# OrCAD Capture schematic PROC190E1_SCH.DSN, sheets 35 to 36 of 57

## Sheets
35 36. CPSW3G RGMII_1: size C; title: ETHERNET EXPANSION CONNECTOR CPSW3G RGMII 1
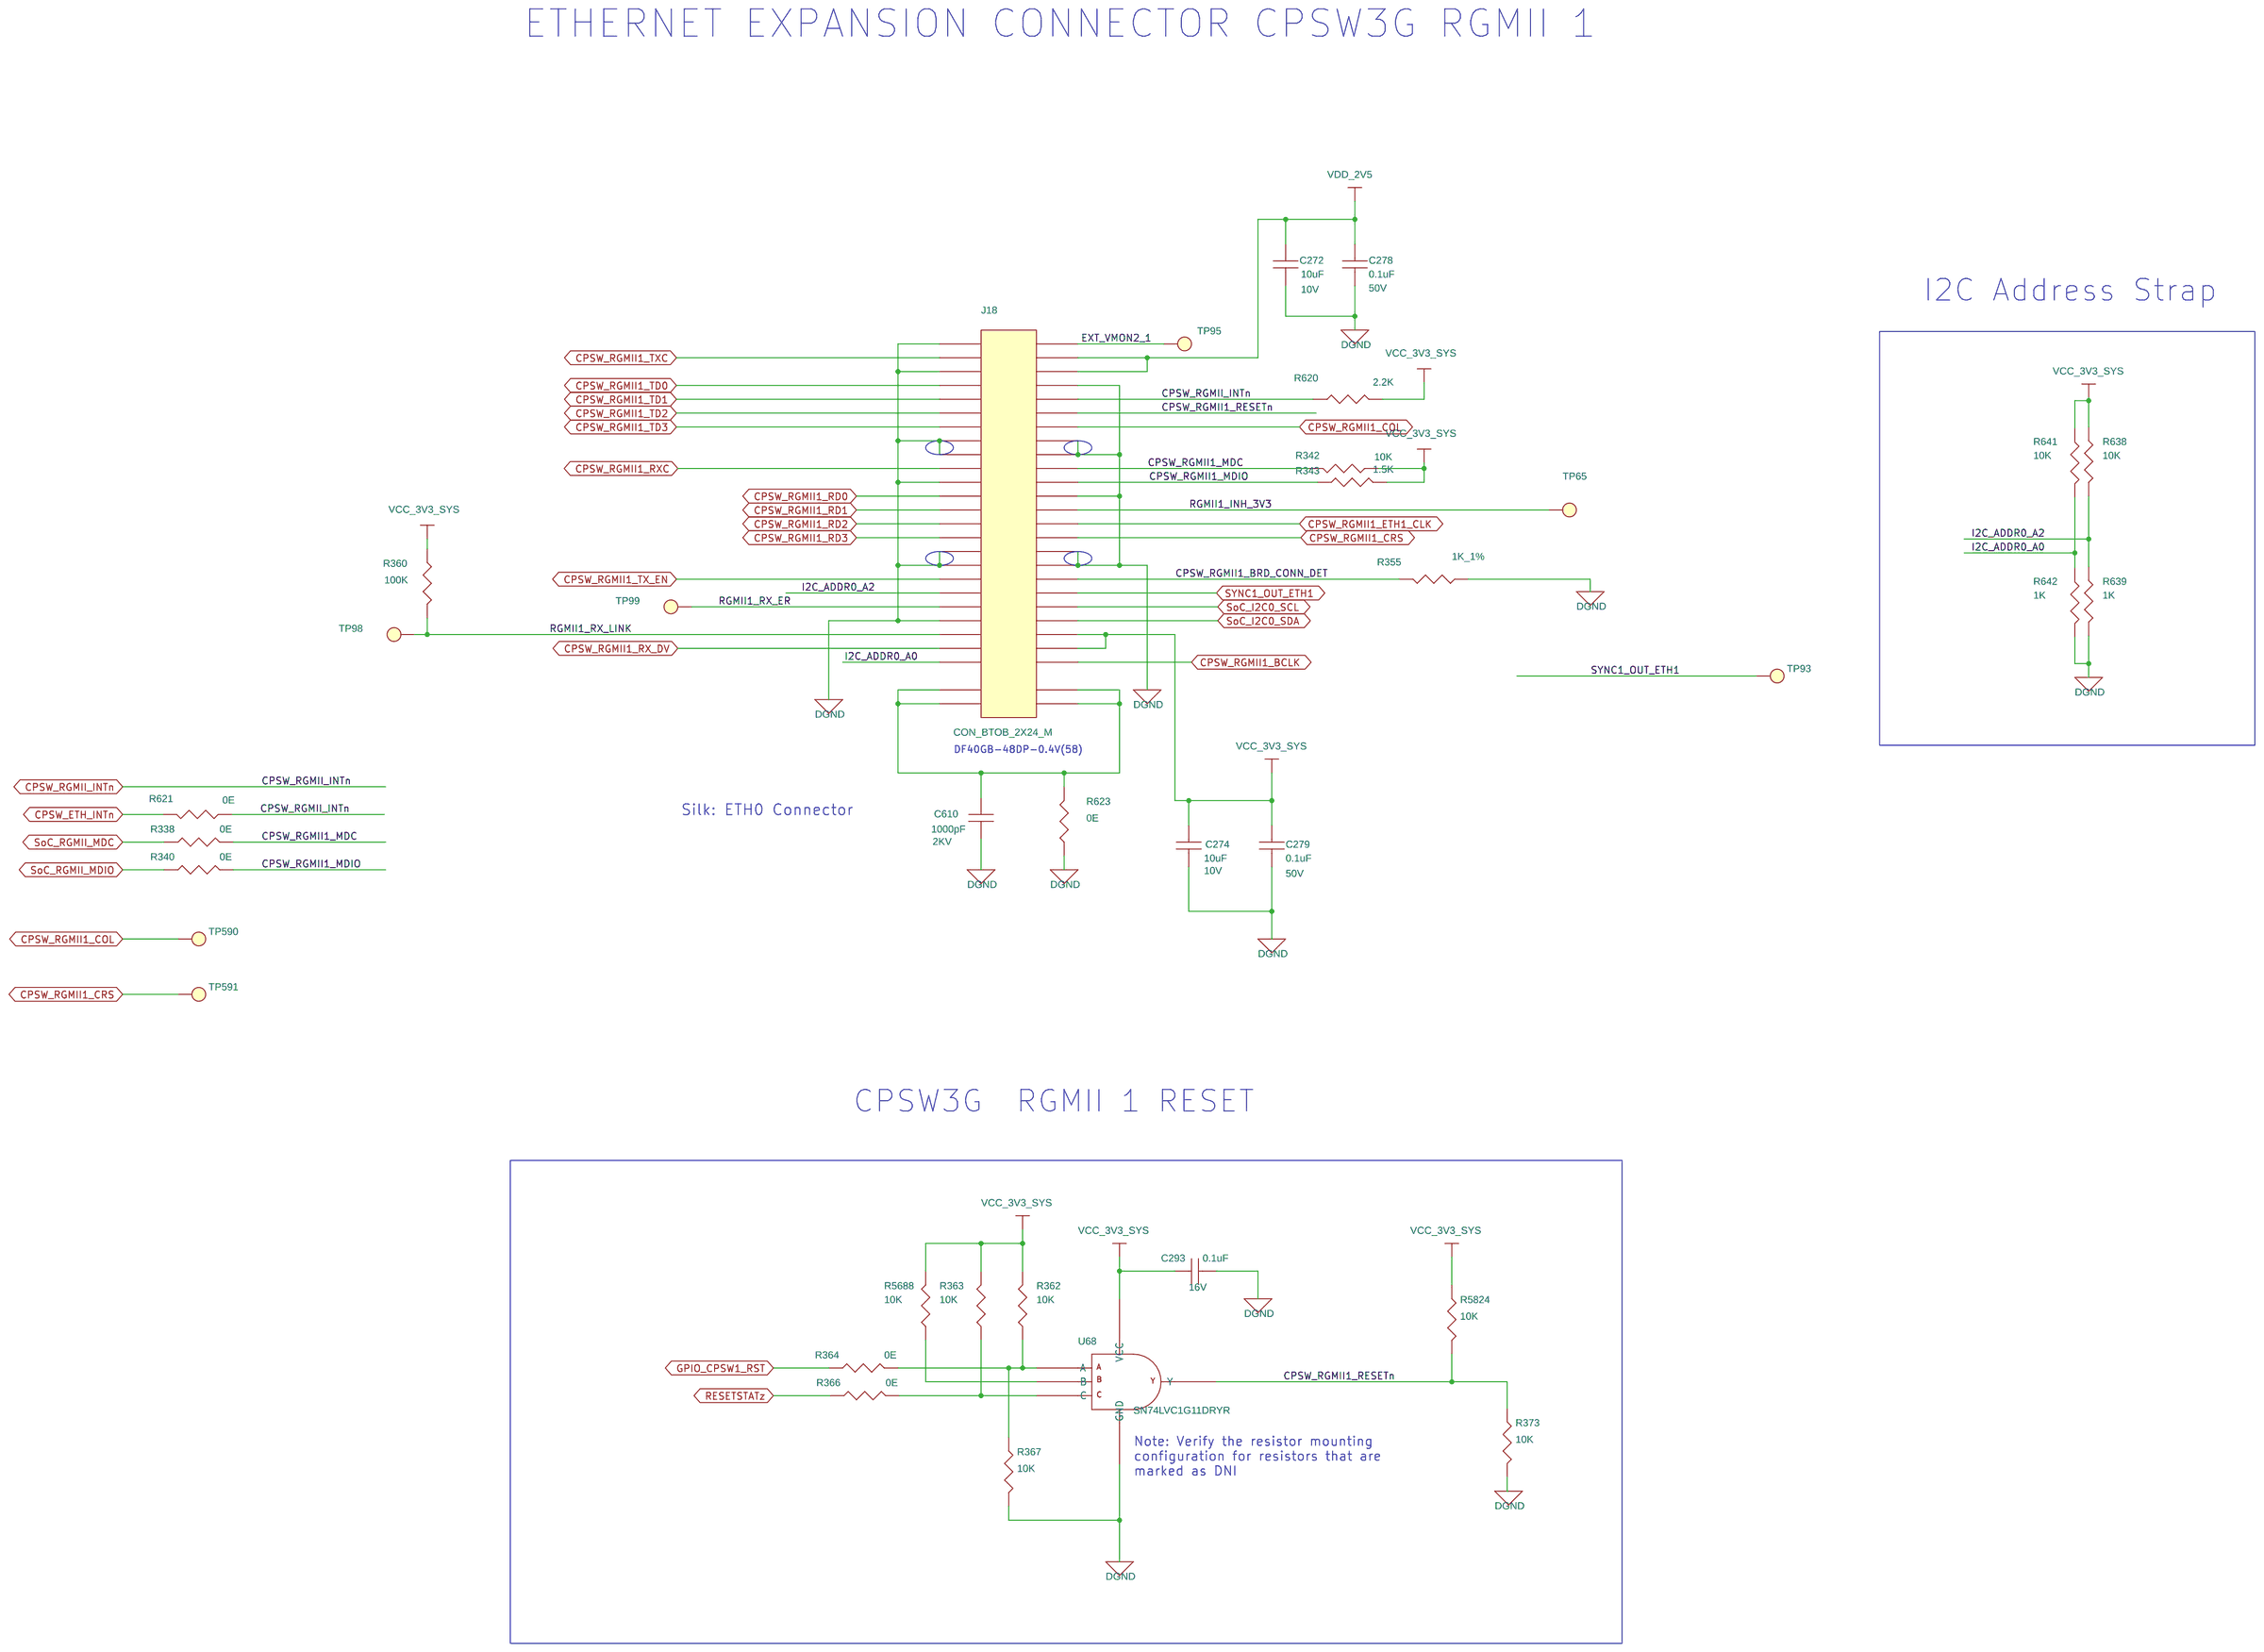
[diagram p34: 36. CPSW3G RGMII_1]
36 37. CPSW3G RGMII_2: size C; title: ETHERNET EXPANSION CONNECTOR CPSW3G RGMII 2
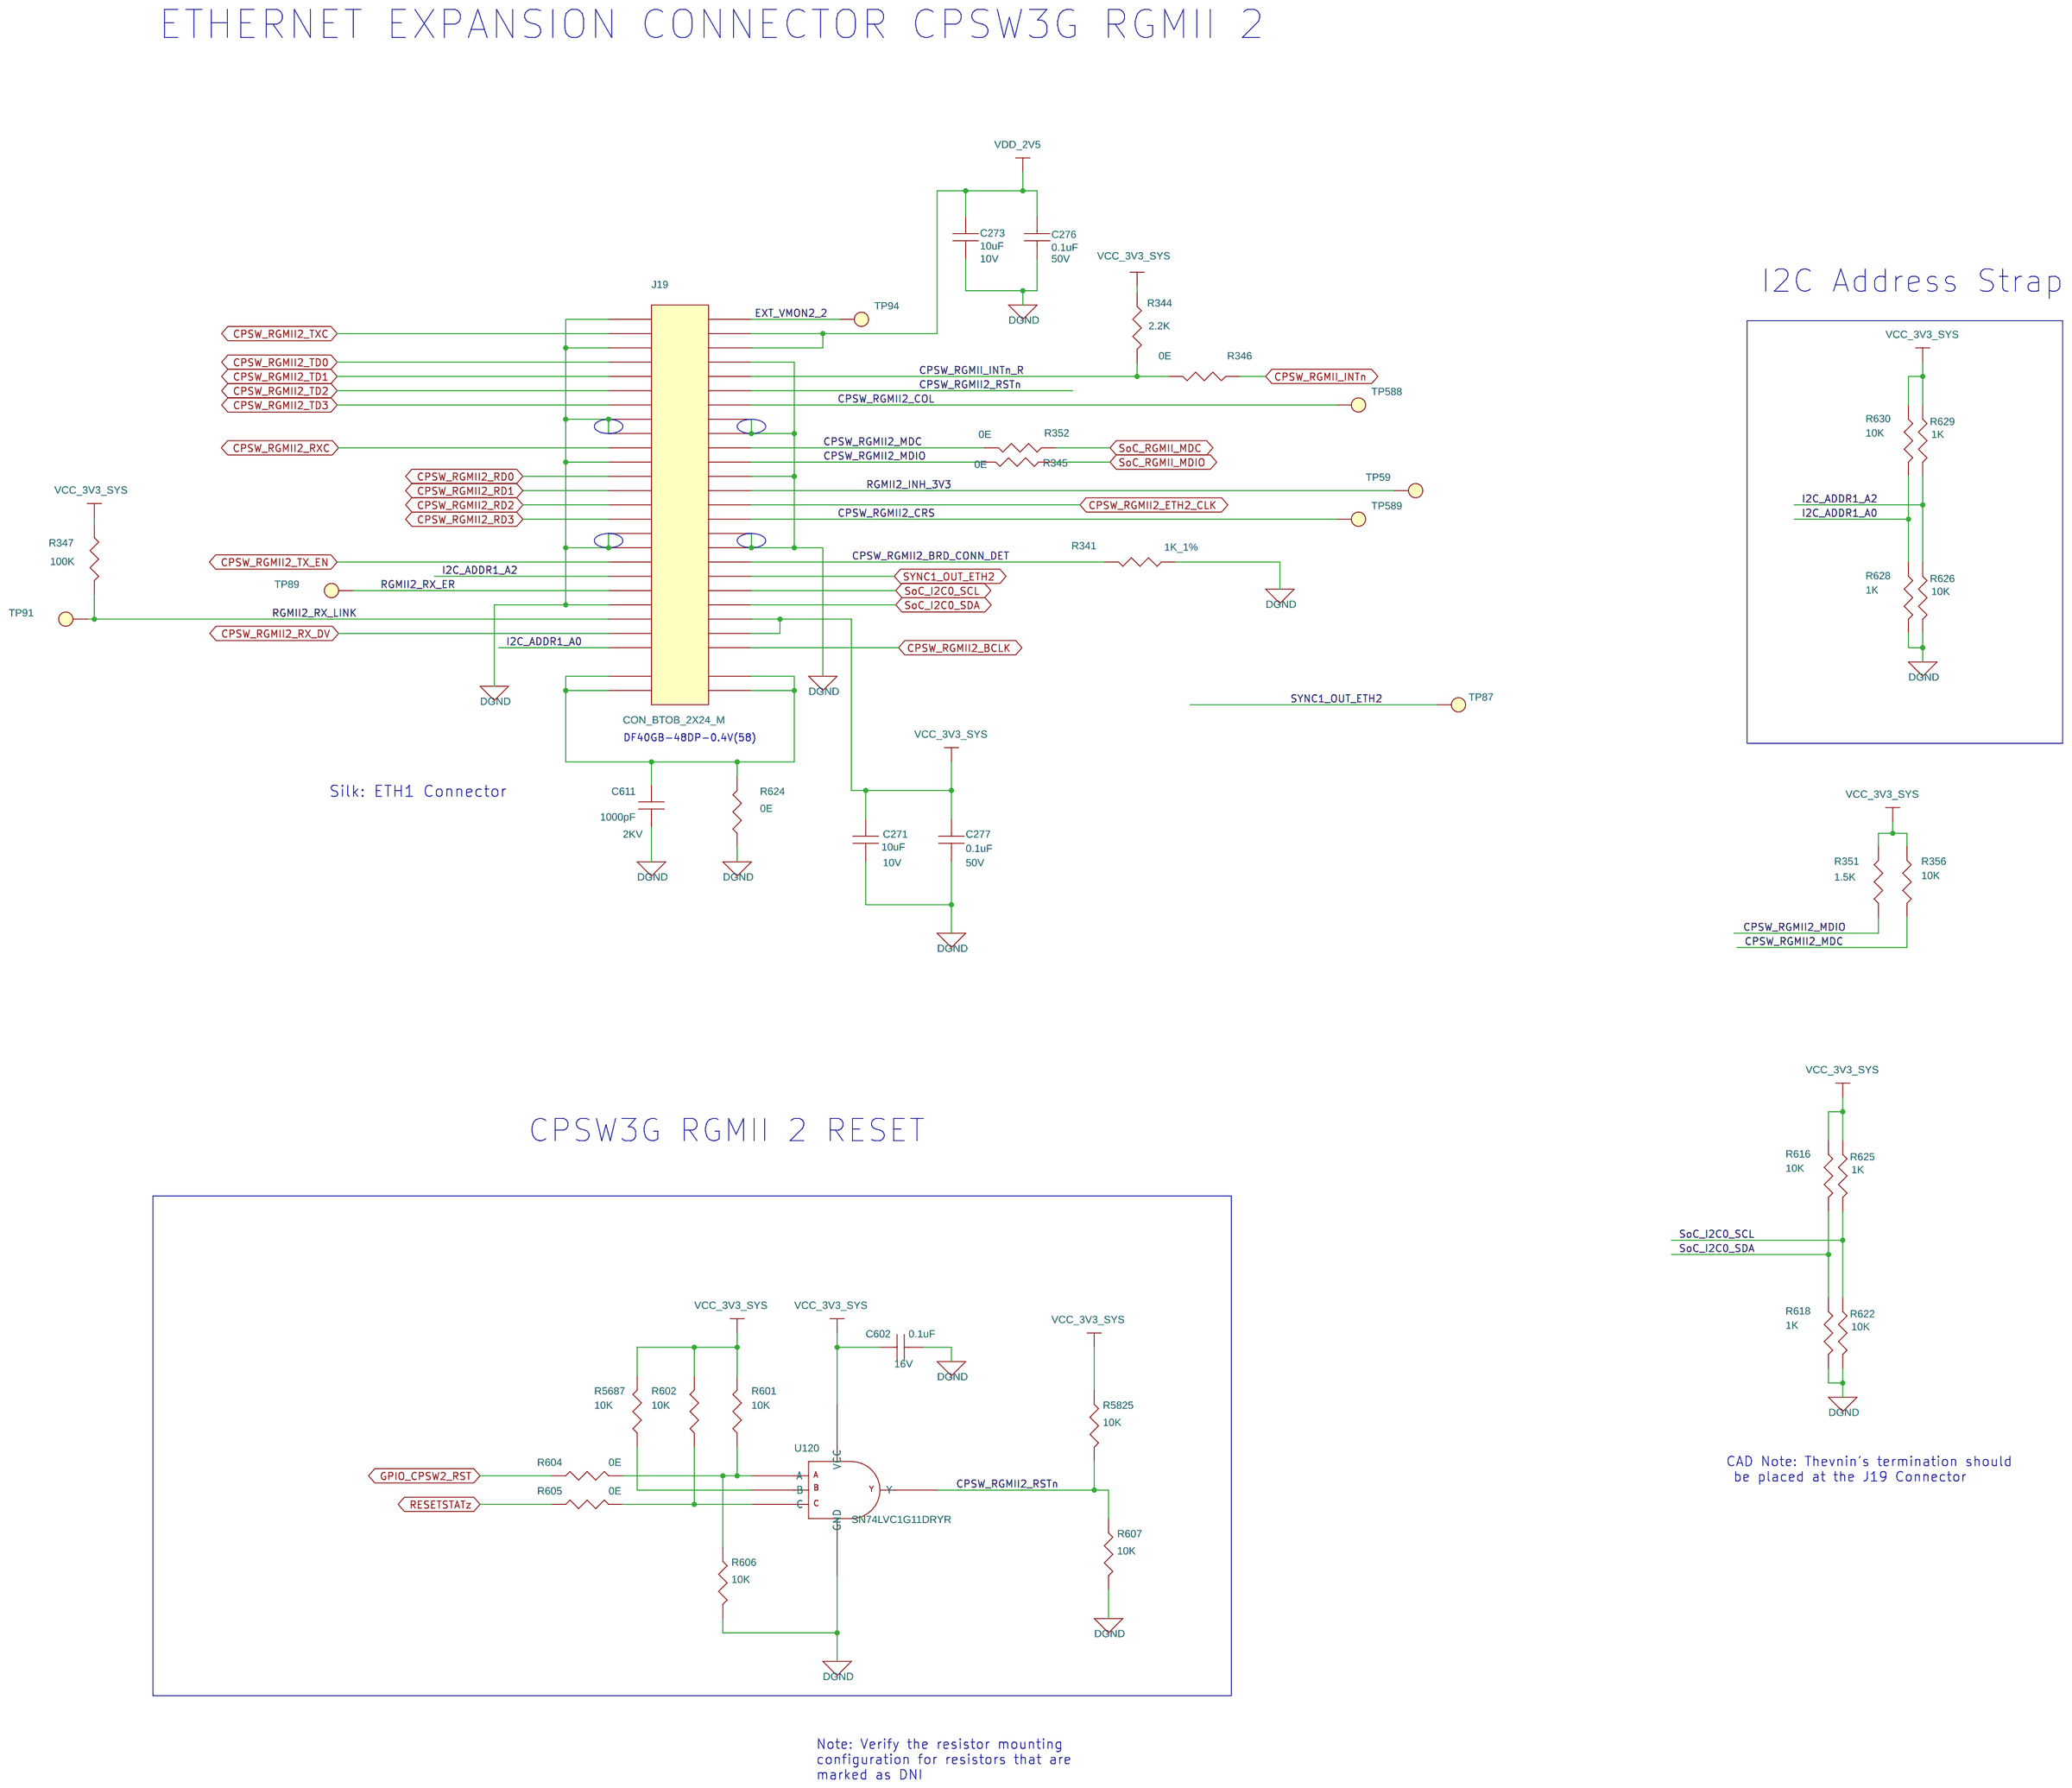
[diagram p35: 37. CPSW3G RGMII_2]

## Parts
sheet 36. CPSW3G RGMII_1
C272  10uF  [CAP0402_0-75]
C274  10uF  [CAP0402_0-75]
C278  0.1uF  [CAP0402_0-75]
C279  0.1uF  [CAP0402_0-75]
C293  0.1uF  [CAP0201_0-5]
C610  1000pF  [CAP1206_1-75]
J18  CON_BTOB_2X24_M  [CON_BTOB2X24_DF40GB-48DP_P_S_S_1-3]
R338  0E  [RES0402_0-5]
R340  0E  [RES0402_0-5]
R342  10K  [RES0201_0-5]
R343  1.5K  [RES0201_0-5]
R355  1K_1%  [RES0402_0-5]
R360  100K  [RES0201_0-5]
R362  10K  [RES0201_0-5]
R363  10K  [RES0201_0-5]
R364  0E  [RES0201_0-5]
R366  0E  [RES0201_0-5]
R367  10K  [RES0201_0-5]
R373  10K  [RES0201_0-5]
R620  2.2K  [RES0201_0-5]
R621  0E  [RES0201_0-5]
R623  0E  [RES0201_0-5]
R638  10K  [RES0402_0-5]
R639  1K  [RES0402_0-5]
R641  10K  [RES0402_0-5]
R642  1K  [RES0402_0-5]
R5688  10K  [RES0201_0-5]
R5824  10K  [RES0201_0-5]
TP65  TP30_SMD  [TP30_SMD]
TP93  TP30_SMD  [TP30_SMD]
TP95  TP30_SMD  [TP30_SMD]
TP98  TP30_SMD  [TP30_SMD]
TP99  TP30_SMD  [TP30_SMD]
TP590  TP30_SMD  [TP30_SMD]
TP591  TP30_SMD  [TP30_SMD]
U68  SN74LVC1G11DRYR  [SON6_SN74LVC2G17_40X60_0-6]
sheet 37. CPSW3G RGMII_2
C271  10uF  [CAP0402_0-75]
C273  10uF  [CAP0402_0-75]
C276  0.1uF  [CAP0402_0-75]
C277  0.1uF  [CAP0402_0-75]
C602  0.1uF  [CAP0201_0-5]
C611  1000pF  [CAP1206_1-75]
J19  CON_BTOB_2X24_M  [CON_BTOB2X24_DF40GB-48DP_P_S_S_1-3]
R341  1K_1%  [RES0402_0-5]
R344  2.2K  [RES0201_0-5]
R345  0E  [RES0201_0-5]
R346  0E  [RES0201_0-5]
R347  100K  [RES0201_0-5]
R351  1.5K  [RES0201_0-5]
R352  0E  [RES0201_0-5]
R356  10K  [RES0201_0-5]
R601  10K  [RES0201_0-5]
R602  10K  [RES0201_0-5]
R604  0E  [RES0201_0-5]
R605  0E  [RES0201_0-5]
R606  10K  [RES0201_0-5]
R607  10K  [RES0201_0-5]
R616  10K  [RES0402_0-5]
R618  1K  [RES0402_0-5]
R622  10K  [RES0402_0-5]
R624  0E  [RES0201_0-5]
R625  1K  [RES0402_0-5]
R626  10K  [RES0402_0-5]
R628  1K  [RES0402_0-5]
R629  1K  [RES0402_0-5]
R630  10K  [RES0402_0-5]
R5687  10K  [RES0201_0-5]
R5825  10K  [RES0201_0-5]
TP59  TP30_SMD  [TP30_SMD]
TP87  TP30_SMD  [TP30_SMD]
TP89  TP30_SMD  [TP30_SMD]
TP91  TP30_SMD  [TP30_SMD]
TP94  TP30_SMD  [TP30_SMD]
TP588  TP30_SMD  [TP30_SMD]
TP589  TP30_SMD  [TP30_SMD]
U120  SN74LVC1G11DRYR  [SON6_SN74LVC2G17_40X60_0-6]

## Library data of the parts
C271-C274 = CAP: CAP CERAMIC 10uF 10V 20% X5R 0402; Chkd/date: PRADEEP/130623; Crtd /date: PRADEEP/130623; Custom_Duty: 15%; Customs_HS_Code: 85322990; Distributor_name: NA; Distributor_part_number: NA; Footprint Path: Y:\MIS_DATABASE\Library\ALTIUM_TOOL\PCB_FOOTPRINTS\Altium_Footprint_Lib.PcbLib; Height: 0.55MM; Library Path: Y:\MIS_DATABASE\Library\ALTIUM_TOOL\SCHEMATICS_PARTS\MS_DISCRETE_Library.schlib; Mfr_name: MURATA; Mfr_part_number: GRM155R61A106ME18; Mistral Part No: 120022060018-R; Package: 0402; Part_type: CAPACITORS\CERAMIC; Project: AM62P_SK; RoHS: RoHS; Temperature: -55°C+85°C; Tolerance: 20%; Voltage: 10V; Wattage: NA; Weight: 6mg; Datasheet: Y:\MIS_DATABASE\DATASHEETS\CAPACITORS\MURATA-GXX-SER_NOV17.PDF
C276-C279 = CAP: CAP CERAMIC 0.1uF 50V 10% X7R 0402; Chkd/date: MANIRAJA/261020; Crtd /date: ALVY/211020; Custom_Duty: 15%; Customs_HS_Code: 85322990; Distributor_name: DIGIKEY; Distributor_part_number: 490-10700-1-ND; Footprint Path: Y:\MIS_DATABASE\Library\ALTIUM_TOOL\PCB_FOOTPRINTS\Altium_Footprint_Lib.PcbLib; Height: 0.55MM; Library Path: Y:\MIS_DATABASE\Library\ALTIUM_TOOL\SCHEMATICS_PARTS\MS_DISCRETE_Library.schlib; Mfr_name: MURATA; Mfr_part_number: GRM155R71H104KE14D; Mistral Part No: 120011100014-R; Package: 0402; Part_type: CAPACITORS\CERAMIC; Project: J7_CP; RoHS: RoHS; Temperature: -55°C+125°C; Tolerance: 10%; Voltage: 50V; Wattage: NA; Weight: 3.1mg; Datasheet: Y:\MIS_DATABASE\DATASHEETS\CAPACITORS\GRM155R71H104KE14.PDF
C293 C602 = CAP: CAP CERAMIC 0.1uF 16V 10% X7S AUTO 0201; Alt_Mfr_name: YAGEO AMERICA; Alt_Mfr_part_number: CC0402KRX5R8BB104; Chkd/date: MANIRAJA/110321; Crtd /date: ALVY/110321; Custom_Duty: 15%; Customs_HS_Code: 85322990; Distributor_name: DIGIKEY; Distributor_part_number: 490-GRT033C71C104KE01DTR-ND; Footprint Path: Y:\MIS_DATABASE\Library\ALTIUM_TOOL\PCB_FOOTPRINTS\Altium_Footprint_Lib.PcbLib; Height: 0.33MM; Library Path: Y:\MIS_DATABASE\Library\ALTIUM_TOOL\SCHEMATICS_PARTS\MS_DISCRETE_Library.schlib; Mfr_name: MURATA; Mfr_part_number: GRT033C71C104KE01D; Mistral Part No: 120021030007-R; Package: 0201; Part_type: CAPACITORS\CERAMIC; Project: J7ES_SK_BRD; RoHS: RoHS; Temperature: -55°C+125°C; Tolerance: 10%; Voltage: 16V; Wattage: NA; Weight: 330mg; Datasheet: Y:\MIS_DATABASE\DATASHEETS\CAPACITORS\GRT033C71C104KE01.PDF
C610 C611 = CAP: CAP CERAMIC 1000pF 2KV 10% X7R 1206; Chkd/date: SHREESHAIL/291106; Crtd /date: MAZHAR/281106; Custom_Duty: 15%; Customs_HS_Code: 85322990; Distributor_name: DIGIKEY; Distributor_part_number: 478-2956-1-ND; Footprint Path: Y:\MIS_DATABASE\Library\ALTIUM_TOOL\PCB_FOOTPRINTS\Altium_Footprint_Lib.PcbLib; Height: 1.52MM; Library Path: Y:\MIS_DATABASE\Library\ALTIUM_TOOL\SCHEMATICS_PARTS\MS_DISCRETE_Library.schlib; Mfr_name: AVX CORPORATION; Mfr_part_number: 1206GC102KAT1A; Mistral Part No: 120015080006-R; Package: 1206; Part_type: CAPACITORS\CERAMIC; Project: ADR1B; RoHS: RoHS; Temperature: -55°C+125°C; Tolerance: 10%; Voltage: 2KV; Wattage: NA; Weight: 16.2mg; Datasheet: Y:\MIS_DATABASE\DATASHEETS\CAPACITORS\AVX_HV-MLC.PDF
J18 J19 = CON_BTOB_24X2_M_SH4: CON BTOB 2X24 0.40MM PITCH MALE ST SMD; Chkd/date: PRAVEEN/290323; Crtd /date: PRAVEEN/290323; Custom_Duty: 24%; Customs_HS_Code: 85369090; Distributor_name: DIGIKEY; Distributor_part_number: H124956CT-ND; Footprint Path: Y:\MIS_DATABASE\Library\ALTIUM_TOOL\PCB_FOOTPRINTS\Altium_Footprint_Lib.PcbLib; Height: 1.30MM; Library Path: Y:\MIS_DATABASE\Library\ALTIUM_TOOL\SCHEMATICS_PARTS\MS_CONNECTOR_Library.schlib; Mfr_name: HIROSE ELECTRIC EUROPE; Mfr_part_number: DF40GB-48DP-0.4V(58); Mistral Part No: 150023030029-R; Package: SMD; Part_type: CONNECTOR\BTOB; Project: AM263P_CC; RoHS: RoHS; Temperature: -35°C+85°C; Tolerance: NA; Voltage: NA; Wattage: NA; Weight: NA; Datasheet: Y:\MIS_DATABASE\DATASHEETS\CONNECTORS\DF40GB-48DP-0.4V.PDF
R338 R340 = RESISTOR: RES 0E 1/10W JUMPER 0402; Chkd/date: VASANTHA/061216; Crtd /date: NAVEED/201014; Custom_Duty: 15%; Customs_HS_Code: 85332119; Distributor_name: DIGIKEY; Distributor_part_number: P0.0JCT-ND; Footprint Path: Y:\MIS_DATABASE\Library\ALTIUM_TOOL\PCB_FOOTPRINTS\Altium_Footprint_Lib.PcbLib; Height: 0.40MM; IBISSP_MODLES: VALUE REPEATING 2 TIME; Library Path: Y:\MIS_DATABASE\Library\ALTIUM_TOOL\SCHEMATICS_PARTS\MS_DISCRETE_Library.schlib; Mfr_name: PANASONIC-ECG; Mfr_part_number: ERJ-2GE0R00X; Mistral Part No: 110018030052-R; Package: 0402; Part_type: RESISTORS\FIXED; Project: AEGIS POM; RoHS: RoHS; Temperature: -55°C+155°C; Tolerance: NA; Voltage: NA; Wattage: 1/10W; Weight: 0.8mg; Datasheet: Y:\MIS_DATABASE\DATASHEETS\RESISTORS\PAN-ERJSER_NOV17.PDF
R342 R356 R362 R363 R367 R373 R601 R602 R606 R607 R5687 R5688 R5824 R5825 = RESISTOR: RES 10K 1/20W 5% 0201; Chkd/date: MANIRAJA/050517; Crtd /date: MANIRAJA/050517; Custom_Duty: 15%; Customs_HS_Code: 85332119; Distributor_name: DIGIKEY; Distributor_part_number: 311-10KNCT-ND; Footprint Path: Y:\MIS_DATABASE\Library\ALTIUM_TOOL\PCB_FOOTPRINTS\Altium_Footprint_Lib.PcbLib; Height: 0.26MM; Library Path: Y:\MIS_DATABASE\Library\ALTIUM_TOOL\SCHEMATICS_PARTS\MS_DISCRETE_Library.schlib; Mfr_name: YAGEO AMERICA; Mfr_part_number: RC0201JR-0710KL; Mistral Part No: 110010070051-R; Package: 0201; Part_type: RESISTORS\FIXED; Project: GOLDEN-I LITE; RoHS: RoHS; Temperature: -55°C+125°C; Tolerance: 5%; Voltage: NA; Wattage: 1/20W; Weight: 0.17mg; Datasheet: Y:\MIS_DATABASE\DATASHEETS\RESISTORS\RCXXXXL-SER_MAR18.PDF
R343 = RESISTOR: RES 1.5K 1/20W 5% 0201; Chkd/date: ALVY/070422; Crtd /date: TAMILARASU/070422; Custom_Duty: 15%; Customs_HS_Code: 85332119; Distributor_name: DIGIKEY; Distributor_part_number: 311-1.5KNCT-ND; Footprint Path: Y:\MIS_DATABASE\Library\ALTIUM_TOOL\PCB_FOOTPRINTS\Altium_Footprint_Lib.PcbLib; Height: 0.26MM; Library Path: Y:\MIS_DATABASE\Library\ALTIUM_TOOL\SCHEMATICS_PARTS\MS_DISCRETE_Library.schlib; Mfr_name: YAGEO AMERICA; Mfr_part_number: RC0201JR-071K5L; Mistral Part No: 110010070057-R; Package: 0201; Part_type: RESISTORS\FIXED; Project: TI_AM62x_SKEVM_BRD; RoHS: RoHS; Temperature: -55°C+125°C; Tolerance: 5%; Voltage: NA; Wattage: 1/20W; Weight: 0.17mg; Datasheet: Y:\MIS_DATABASE\DATASHEETS\RESISTORS\RCXXXXL-SER_MAR18.PDF
R341 R355 = RESISTOR: RES 1K 1/10W 1% 0402; Chkd/date: VASANTHA/281216; Crtd /date: MAZHAR/150506; Custom_Duty: 15%; Customs_HS_Code: 85332119; Distributor_name: DIGIKEY; Distributor_part_number: P1.00KLCT-ND; Footprint Path: Y:\MIS_DATABASE\Library\ALTIUM_TOOL\PCB_FOOTPRINTS\Altium_Footprint_Lib.PcbLib; Height: 0.40MM; Library Path: Y:\MIS_DATABASE\Library\ALTIUM_TOOL\SCHEMATICS_PARTS\MS_DISCRETE_Library.schlib; Mfr_name: PANASONIC-ECG; Mfr_part_number: ERJ-2RKF1001X; Mistral Part No: 110009030411-R; Package: 0402; Part_type: RESISTORS\FIXED; Project: VOCERA; RoHS: RoHS; Temperature: -55°C+155°C; Tolerance: 1%; Voltage: NA; Wattage: 1/10W; Weight: 0.8mg; Datasheet: Y:\MIS_DATABASE\DATASHEETS\RESISTORS\PAN-ERJSER_NOV17.PDF
R347 R360 = RESISTOR: RES 100K 1/20W 5% 0201; Chkd/date: MANIRAJA/050517; Crtd /date: MANIRAJA/050517; Custom_Duty: 15%; Customs_HS_Code: 85332119; Distributor_name: DIGIKEY; Distributor_part_number: 311-100KNCT-ND; Footprint Path: Y:\MIS_DATABASE\Library\ALTIUM_TOOL\PCB_FOOTPRINTS\Altium_Footprint_Lib.PcbLib; Height: 0.26MM; Library Path: Y:\MIS_DATABASE\Library\ALTIUM_TOOL\SCHEMATICS_PARTS\MS_DISCRETE_Library.schlib; Mfr_name: YAGEO AMERICA; Mfr_part_number: RC0201JR-07100KL; Mistral Part No: 110009030176-R; Package: 0201; Part_type: RESISTORS\FIXED; Project: GOLDEN-I LITE; RoHS: RoHS; Temperature: -55°C+125°C; Tolerance: 5%; Voltage: NA; Wattage: 1/20W; Weight: 0.17mg; Datasheet: Y:\MIS_DATABASE\DATASHEETS\RESISTORS\RCXXXXL-SER_MAR18.PDF
R345 R346 R352 R364 R366 R604 R605 R621 R623 R624 = RESISTOR: RES 0E 1/20W 5% 0201; Chkd/date: NAVEED/301214; Crtd /date: MUDDU/120710; Custom_Duty: 15%; Customs_HS_Code: 85332119; Distributor_name: DIGIKEY; Distributor_part_number: 311-0.0NCT-ND; Footprint Path: Y:\MIS_DATABASE\Library\ALTIUM_TOOL\PCB_FOOTPRINTS\Altium_Footprint_Lib.PcbLib; Height: 0.26MM; Library Path: Y:\MIS_DATABASE\Library\ALTIUM_TOOL\SCHEMATICS_PARTS\MS_DISCRETE_Library.schlib; Mfr_name: YAGEO AMERICA; Mfr_part_number: RC0201JR-070RL; Mistral Part No: 110010070067-R; Package: 0201; Part_type: RESISTORS\FIXED; Project: PB_BUGBASE; RoHS: RoHS; Temperature: -55°C+125°C; Tolerance: 5%; Voltage: NA; Wattage: 1/20W; Weight: 0.17mg; Datasheet: Y:\MIS_DATABASE\DATASHEETS\RESISTORS\RCXXXXL-SER_MAR18.PDF
R344 R620 = RESISTOR: RES 2.2K 1/20W 5% 0201; Chkd/date: MANIRAJA/050517; Crtd /date: MANIRAJA/050517; Custom_Duty: 15%; Customs_HS_Code: 85332119; Distributor_name: DIGIKEY; Distributor_part_number: 311-2.2KNCT-ND; Footprint Path: Y:\MIS_DATABASE\Library\ALTIUM_TOOL\PCB_FOOTPRINTS\Altium_Footprint_Lib.PcbLib; Height: 0.26MM; Library Path: Y:\MIS_DATABASE\Library\ALTIUM_TOOL\SCHEMATICS_PARTS\MS_DISCRETE_Library.schlib; Mfr_name: YAGEO AMERICA; Mfr_part_number: RC0201JR-072K2L; Mistral Part No: 110009030427-R; Package: 0201; Part_type: RESISTORS\FIXED; Project: GOLDEN-I LITE; RoHS: RoHS; Temperature: -55°C+125°C; Tolerance: 5%; Voltage: NA; Wattage: 1/20W; Weight: 0.17mg; Datasheet: Y:\MIS_DATABASE\DATASHEETS\RESISTORS\RCXXXXL-SER_MAR18.PDF
R616 R622 R626 R630 R638 R641 = RESISTOR: RES 10K 1/16W 5% 0402; Chkd/date: VASANTHA/061216; Crtd /date: MAZHAR/230805; Custom_Duty: 15%; Customs_HS_Code: 85332119; Distributor_name: DIGIKEY; Distributor_part_number: 311-10KJRCT-ND; Footprint Path: Y:\MIS_DATABASE\Library\ALTIUM_TOOL\PCB_FOOTPRINTS\Altium_Footprint_Lib.PcbLib; Height: 0.40MM; Library Path: Y:\MIS_DATABASE\Library\ALTIUM_TOOL\SCHEMATICS_PARTS\MS_DISCRETE_Library.schlib; Mfr_name: YAGEO AMERICA; Mfr_part_number: RC0402JR-0710KL; Mistral Part No: 110011060021-R; Package: 0402; Part_type: RESISTORS\FIXED; Project: HSE; RoHS: RoHS; Temperature: -55°C+155°C; Tolerance: 5%; Voltage: NA; Wattage: 1/16W; Weight: 0.65mg; Datasheet: Y:\MIS_DATABASE\DATASHEETS\RESISTORS\RCXXXXL-SER_MAR18.PDF
R618 R625 R628 R629 R639 R642 = RESISTOR: RES 1K 1/10W 5% 0402; Chkd/date: VASANTHA/201216; Crtd /date: MAZHAR/230805; Custom_Duty: 15%; Customs_HS_Code: 85332119; Distributor_name: DIGIKEY; Distributor_part_number: P1.0KJCT-ND; Footprint Path: Y:\MIS_DATABASE\Library\ALTIUM_TOOL\PCB_FOOTPRINTS\Altium_Footprint_Lib.PcbLib; Height: 0.40MM; Library Path: Y:\MIS_DATABASE\Library\ALTIUM_TOOL\SCHEMATICS_PARTS\MS_DISCRETE_Library.schlib; Mfr_name: PANASONIC-ECG; Mfr_part_number: ERJ-2GEJ102X; Mistral Part No: 110009030400-R; Package: 0402; Part_type: RESISTORS\FIXED; Project: HSE; RoHS: RoHS; Temperature: -55°C+155°C; Tolerance: 5%; Voltage: NA; Wattage: 1/10W; Weight: 0.8mg; Datasheet: Y:\MIS_DATABASE\DATASHEETS\RESISTORS\PAN-ERJSER_NOV17.PDF
TP59 TP65 TP87 TP89 TP91 TP93-TP95 TP98 TP99 TP588-TP591 = TESTPOINT: TESTPOINT CIR 30 SMD; Chkd/date: SHREESHAIL/171006; Crtd /date: MAZHAR/171006; Custom_Duty: NA; Customs_HS_Code: NA; Distributor_name: NA; Distributor_part_number: NA; Footprint Path: Y:\MIS_DATABASE\Library\ALTIUM_TOOL\PCB_FOOTPRINTS\Altium_Footprint_Lib.PcbLib; Height: NA; Library Path: Y:\MIS_DATABASE\Library\ALTIUM_TOOL\SCHEMATICS_PARTS\MS_DISCRETE_Library.schlib; MECHANICAL 3D STEP FILE: NA; Mfr_name: LOCAL; Mistral Part No: 130009030930; Package: SMD; Project: BT MODULE_CSRBC04; RoHS: NA; Temperature: NA; Tolerance: NA; Voltage: NA; Wattage: NA; Weight: NA; Datasheet: NA
U68 U120 = SN74LVC1G11DCKR_SC70-6: IC SINGLE 3-INPUT POSITIVE-AND GATE SON6; Chkd/date: MANIRAJA/270121; Crtd /date: ALVY/270121; Custom_Duty: 15%; Customs_HS_Code: 85423100; Distributor_name: DIGIKEY; Distributor_part_number: 296-30120-1-ND; Footprint Path: Y:\MIS_DATABASE\Library\ALTIUM_TOOL\PCB_FOOTPRINTS\Altium_Footprint_Lib.PcbLib; Height: 0.60MM; Library Path: Y:\MIS_DATABASE\Library\ALTIUM_TOOL\SCHEMATICS_PARTS\MS_GATE_Library.schlib; Mfr_name: TEXAS INSTRUMENTS; Mistral Part No: 141021010013-R; Package: SON6; Part_type: ICS\DIGITAL\GATES; Project: AM64X_SKEVM; RoHS: RoHS; Temperature: -40°C+125°C; Tolerance: NA; Voltage: NA; Wattage: NA; Weight: 33mg; Datasheet: Y:\MIS_DATABASE\DATASHEETS\ICS\DIGITAL\GATES\SN74LVC1G_NOV16.PDF
R351 = RESISTOR: RES 1.5K 1/20W 5% 0201; Chkd/date: MAZHAR/130208; Crtd /date: USMAN/130208; Custom_Duty: 15%; Customs_HS_Code: 85332119; Distributor_name: DIGIKEY; Distributor_part_number: P1.5KAGCT-ND; Footprint Path: Y:\MIS_DATABASE\Library\ALTIUM_TOOL\PCB_FOOTPRINTS\Altium_Footprint_Lib.PcbLib; Height: 0.26MM; Library Path: Y:\MIS_DATABASE\Library\ALTIUM_TOOL\SCHEMATICS_PARTS\MS_DISCRETE_Library.schlib; Manufacturer: PANASONIC-ECG; Mfr_name: PANASONIC-ECG; Mfr_part_number: ERJ-1GEJ152C; Mistral Part No: 110010070057-R; Package: 0201; Part_type: RESISTORS\FIXED; Project: SMART VIEW_IP CAMERA; RoHS: RoHS; Temperature: -55°C+125°C; Tolerance: 5%; Voltage: NA; Wattage: 1/20W; Weight: 0.15mg; Datasheet: Y:\MIS_DATABASE\DATASHEETS\RESISTORS\PAN-ERJXGE-FEB06.PDF

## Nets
DGND: C271.2 C272.2 C273.2 C274.2 C276.2 C277.2 C278.2 C279.2 C293.2 C602.2 C610.2 C611.2 J18.1 J18.5 J18.8 J18.15 J18.16 J18.17 J18.18 J18.21 J18.24 J18.31 J18.32 J18.33 J18.34 J18.41 J19.1 J19.5 J19.8 J19.15 J19.16 J19.17 J19.18 J19.21 J19.24 J19.31 J19.32 J19.33 J19.34 J19.41 R341.1 R355.1 R367.2 R373.2 R606.2 R607.2 R618.1 R622.1 R623.1 R624.1 R626.1 R628.1 R639.1 R642.1 U68.2(GND) U120.2(GND) ; also on sheet 1 2 12 13 14 15 16 17 18 19 20 21 22 23 24 25 26 27 28 29 31 32 33 34 37 38 39 40 41 42 43 44 45 46 47 48 49 50 51 52 53 54 55 56
VCC_3V3_SYS: C271.1 C274.1 C277.1 C279.1 C293.1 C602.1 J18.44 J18.46 J19.44 J19.46 R342.1 R343.2 R344.1 R347.1 R351.2 R356.1 R360.1 R362.2 R363.2 R601.2 R602.2 R616.2 R620.2 R625.2 R629.2 R630.2 R638.2 R641.2 R5687.2 R5688.2 R5824.1 R5825.1 U68.5(VCC) U120.5(VCC) ; also on sheet 1 2 12 16 17 23 28 29 31 34 38 40 44 47 48 49 50 55 56
VDD_2V5: C272.1 C273.1 C276.1 C278.1 J18.4 J18.6 J19.4 J19.6 ; also on sheet 1
CPSW_ETH_INTn: R621.1 ; also on sheet 23
CPSW_RGMII1_BCLK: J18.48 ; also on sheet 34
CPSW_RGMII1_BRD_CONN_DET: J18.36 R355.2
CPSW_RGMII1_COL: J18.14 TP590.1(TP)
CPSW_RGMII1_CRS: J18.30 TP591.1(TP)
CPSW_RGMII1_ETH1_CLK: J18.28 ; also on sheet 22
CPSW_RGMII1_MDC: J18.20 R338.2 R342.2
CPSW_RGMII1_MDIO: J18.22 R340.2 R343.1
CPSW_RGMII1_RD0: J18.23 ; also on sheet 32
CPSW_RGMII1_RD1: J18.25 ; also on sheet 32
CPSW_RGMII1_RD2: J18.27 ; also on sheet 32
CPSW_RGMII1_RD3: J18.29 ; also on sheet 32
CPSW_RGMII1_RESETn: J18.12 R373.1 R5824.2 U68.4(Y)
CPSW_RGMII1_RX_DV: J18.45 ; also on sheet 32
CPSW_RGMII1_RXC: J18.19 ; also on sheet 32
CPSW_RGMII1_TD0: J18.7 ; also on sheet 32
CPSW_RGMII1_TD1: J18.9 ; also on sheet 32
CPSW_RGMII1_TD2: J18.11 ; also on sheet 32
CPSW_RGMII1_TD3: J18.13 ; also on sheet 32
CPSW_RGMII1_TX_EN: J18.35 ; also on sheet 32
CPSW_RGMII1_TXC: J18.3 ; also on sheet 32
CPSW_RGMII2_BCLK: J19.48 ; also on sheet 34
CPSW_RGMII2_BRD_CONN_DET: J19.36 R341.2
CPSW_RGMII2_COL: J19.14 TP588.1(TP)
CPSW_RGMII2_CRS: J19.30 TP589.1(TP)
CPSW_RGMII2_ETH2_CLK: J19.28 ; also on sheet 22
CPSW_RGMII2_MDC: J19.20 R352.2 R356.2
CPSW_RGMII2_MDIO: J19.22 R345.2 R351.1
CPSW_RGMII2_RD0: J19.23 ; also on sheet 32
CPSW_RGMII2_RD1: J19.25 ; also on sheet 32
CPSW_RGMII2_RD2: J19.27 ; also on sheet 32
CPSW_RGMII2_RD3: J19.29 ; also on sheet 32
CPSW_RGMII2_RSTn: J19.12 R607.1 R5825.2 U120.4(Y)
CPSW_RGMII2_RX_DV: J19.45 ; also on sheet 32
CPSW_RGMII2_RXC: J19.19 ; also on sheet 32
CPSW_RGMII2_TD0: J19.7 ; also on sheet 32
CPSW_RGMII2_TD1: J19.9 ; also on sheet 32
CPSW_RGMII2_TD2: J19.11 ; also on sheet 32
CPSW_RGMII2_TD3: J19.13 ; also on sheet 32
CPSW_RGMII2_TX_EN: J19.35 ; also on sheet 32
CPSW_RGMII2_TXC: J19.3 ; also on sheet 32
CPSW_RGMII_INTn: J18.10 R346.1 R620.1 R621.2
CPSW_RGMII_INTn_R: J19.10 R344.2 R346.2
EXT_VMON2_1: J18.2 TP95.1(TP)
EXT_VMON2_2: J19.2 TP94.1(TP)
GPIO_CPSW1_RST: R364.1 ; also on sheet 47
GPIO_CPSW2_RST: R604.1 ; also on sheet 47
I2C_ADDR0_A0: J18.47 R641.1 R642.2
I2C_ADDR0_A2: J18.37 R638.1 R639.2
I2C_ADDR1_A0: J19.47 R628.2 R630.1
I2C_ADDR1_A2: J19.37 R626.2 R629.1
RESETSTATz: R366.1 R605.1 ; also on sheet 23 47
RGMII1_INH_3V3: J18.26 TP65.1(TP)
RGMII1_RX_ER: J18.39 TP99.1(TP)
RGMII1_RX_LINK: J18.43 R360.2 TP98.1(TP)
RGMII2_INH_3V3: J19.26 TP59.1(TP)
RGMII2_RX_ER: J19.39 TP89.1(TP)
RGMII2_RX_LINK: J19.43 R347.2 TP91.1(TP)
SoC_I2C0_SCL: J18.40 J19.40 R622.2 R625.1 ; also on sheet 12 47 48 49 50 55
SoC_I2C0_SDA: J18.42 J19.42 R616.1 R618.2 ; also on sheet 12 47 48 49 50 55
SoC_RGMII_MDC: R338.1 R352.1 ; also on sheet 21
SoC_RGMII_MDIO: R340.1 R345.1 ; also on sheet 21
SYNC1_OUT_ETH1: J18.38 TP93.1(TP) ; also on sheet 31
SYNC1_OUT_ETH2: J19.38 TP87.1(TP) ; also on sheet 31
N17269599: R363.1 R366.2 U68.6(C)
N17269609: R362.1 R364.2 R367.1 U68.1(A)
N22498870: R602.1 R605.2 U120.6(C)
N22498881: R601.1 R604.2 R606.1 U120.1(A)
N25809420: C610.1 J18.SH1 J18.SH2 J18.SH3 J18.SH4 R623.2
N25815350: C611.1 J19.SH1 J19.SH2 J19.SH3 J19.SH4 R624.2
N28084995: R5687.1 U120.3(B)
N28086994: R5688.1 U68.3(B)

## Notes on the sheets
sheet 35
- ETHERNET EXPANSION CONNECTOR CPSW3G RGMII 1
- I2C Address Strap
- DF40GB-48DP-0.4V(58)
- Silk: ETH0 Connector
- CPSW3G  RGMII 1 RESET
- Note: Verify the resistor mounting
  configuration for resistors that are
  marked as DNI
sheet 36
- ETHERNET EXPANSION CONNECTOR CPSW3G RGMII 2
- I2C Address Strap
- DF40GB-48DP-0.4V(58)
- Silk: ETH1 Connector
- CPSW3G RGMII 2 RESET
- CAD Note: Thevnin's termination should
   be placed at the J19 Connector
- Note: Verify the resistor mounting
  configuration for resistors that are
  marked as DNI
